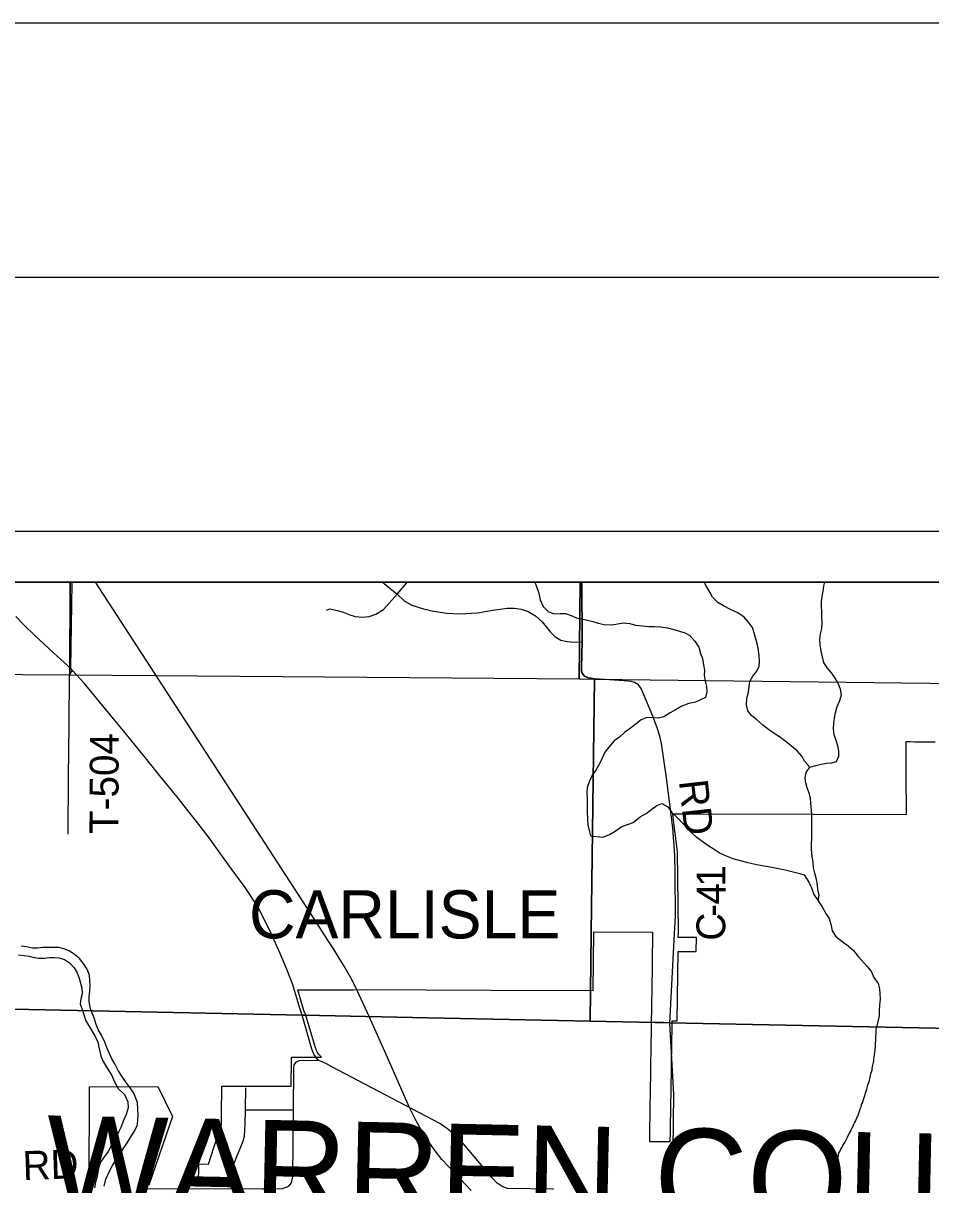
# Model space of a CAD drawing. Extents: x -7.3 to 34, y 0 to 22.
# Drawn here: x 3.68 to 5.466, y 19.714 to 22 of the extents above; entities that cross this region are included whole.
import ezdxf

# ---------------------------------------------------------------- set-up
doc = ezdxf.new("R2010")
doc.units = 0
for name, color, linetype in [('GM_X_City_Street', 7, 'Continuous'), ('GM_X_Corporation', 7, 'Continuous'), ('GM_X_Corporation_Text', 7, 'Continuous'), ('GM_X_County_Road', 7, 'Continuous'), ('GM_X_County_Road_Text', 7, 'Continuous'), ('GM_X_County_Text', 7, 'Continuous'), ('GM_X_Major_River', 7, 'Continuous'), ('GM_X_Minor_River', 7, 'Continuous'), ('GM_X_Rail_Line', 7, 'Continuous'), ('GM_X_State_Route', 7, 'Continuous'), ('GM_X_Township_Road', 7, 'Continuous'), ('GM_X_Township_Road_Text', 7, 'Continuous'), ('SH_Border', 7, 'Continuous'), ('SH_Cut_Line', 7, 'Continuous'), ('SH_Data', 7, 'Continuous')]:
    doc.layers.add(name, color=color, linetype=linetype)

msp = doc.modelspace()

# ---------------------------------------------------------------- linework, layer by layer
at = {"layer": 'GM_X_City_Street'}
for p, q in [((4.1178, 19.8612), (4.2121, 19.8615)), ((5.4549, 19.699), (5.4555, 19.7719))]:
    msp.add_line(p, q, dxfattribs=at)
msp.add_lwpolyline([(4.0902, 19.7065), (4.0892, 19.7344), (4.0911, 19.7458), (4.0946, 19.7551), (4.1131, 19.8), (4.1159, 19.8095), (4.1172, 19.833), (4.1178, 19.8612), (4.1185, 19.9047)], dxfattribs=at)
at = {"layer": 'GM_X_Corporation'}
for points in [[(2.7422, 20.0783), (4.2288, 20.048), (4.2328, 20.0479), (4.4762, 20.0428), (4.7954, 20.036), (4.9235, 20.0334), (4.9401, 20.0331), (4.9519, 20.0328), (5.8024, 20.0153), (5.9388, 20.0125), (6.0214, 20.0108), (6.0677, 20.0098), (6.0763, 20.0096), (6.4154, 20.0027), (6.4242, 20.0024), (6.9507, 19.9888), (6.9988, 19.9839), (7.6051, 19.9224), (7.8469, 19.8978), (8.8913, 19.7872), (8.9, 19.7858), (8.9, 20.9), (2.1, 20.9)], [(8.9, 20.9), (4.7796, 20.9), (4.7799, 20.7827), (4.7788, 20.7319), (4.7788, 20.7252), (4.7798, 20.7211), (4.7847, 20.7149), (4.7927, 20.7114), (4.804, 20.71), (4.7977, 20.2101), (4.7954, 20.036), (4.9235, 20.0334), (4.9401, 20.0331), (4.9519, 20.0328), (5.8024, 20.0153), (5.9388, 20.0125), (6.0214, 20.0108), (6.0677, 20.0098), (6.0763, 20.0096), (6.4154, 20.0027), (6.4242, 20.0024), (6.9507, 19.9888), (6.9988, 19.9839), (7.6051, 19.9224)], [(4.0254, 19.7132), (4.0256, 19.7549), (4.0446, 19.7548), (4.0553, 19.7873), (4.0612, 19.8053), (4.0659, 19.8198), (4.0701, 19.8323), (4.0703, 19.8512), (4.0706, 19.8702), (4.0708, 19.8891), (4.0711, 19.908), (4.1128, 19.9079), (4.1241, 19.9079), (4.1658, 19.9078), (4.2075, 19.9077), (4.2083, 19.9597), (4.2083, 19.9649), (4.254, 19.9651), (4.2672, 19.9653), (4.2656, 19.9665), (4.2636, 19.9681), (4.2621, 19.9698), (4.2612, 19.9712), (4.2595, 19.9742), (4.2575, 19.9779), (4.2564, 19.9806), (4.2554, 19.9837), (4.2354, 20.0499), (4.2347, 20.0502), (4.2327, 20.0567), (4.2203, 20.0974), (4.3008, 20.0977), (4.3242, 20.0979), (4.3301, 20.0979), (4.344, 20.098), (4.6011, 20.0967), (4.8019, 20.0965), (4.8029, 20.2118), (4.9168, 20.2113), (4.9185, 20.2112), (4.9182, 20.1896), (4.9182, 20.1887), (4.9179, 20.1706), (4.9179, 20.1698), (4.9177, 20.1516), (4.9177, 20.1508), (4.9174, 20.1326), (4.9174, 20.1319), (4.9171, 20.1136), (4.9171, 20.113), (4.9169, 20.0946), (4.9169, 20.094), (4.9166, 20.0756), (4.9166, 20.0751), (4.9163, 20.0566), (4.9163, 20.0562), (4.9159, 20.0378), (4.9156, 20.0212), (4.9156, 20.0189), (4.9154, 20.0045), (4.9153, 19.9999), (4.9151, 19.9878), (4.915, 19.981), (4.9148, 19.9711), (4.9147, 19.9602), (4.9146, 19.9545), (4.9145, 19.9507), (4.9143, 19.9378), (4.9142, 19.9317), (4.9141, 19.9211), (4.9139, 19.9128), (4.9138, 19.9044), (4.9136, 19.8939), (4.9136, 19.8884), (4.9133, 19.8749), (4.9133, 19.8712), (4.913, 19.856), (4.9128, 19.8408), (4.9127, 19.8371), (4.9126, 19.8257), (4.9125, 19.8181), (4.9122, 19.7992), (4.9516, 19.799), (4.9534, 19.799), (4.9537, 19.818), (4.954, 19.8369), (4.9543, 19.8558), (4.9546, 19.8748), (4.9549, 19.8937), (4.9552, 19.9126), (4.9555, 19.9316), (4.9558, 19.9505), (4.9559, 19.96), (4.9562, 19.9802), (4.9565, 19.9991), (4.9568, 20.0181), (4.9573, 20.0365), (4.963, 20.0364), (4.9668, 20.0363), (4.9668, 20.0365), (4.9687, 20.1733), (4.9977, 20.1729), (5.0043, 20.1728), (5.0043, 20.1736), (5.0047, 20.2003), (4.9986, 20.2004), (4.9981, 20.2004), (4.974, 20.2007), (4.9691, 20.2008), (4.9691, 20.2015), (4.9692, 20.2111), (4.9687, 20.2654), (4.9677, 20.369), (4.963, 20.4061), (4.9619, 20.4154), (4.9583, 20.4438), (4.9611, 20.4438), (4.9617, 20.4438), (4.9653, 20.4438), (4.9658, 20.4438), (4.9807, 20.4438), (4.9853, 20.4438), (5.2342, 20.4433), (5.4178, 20.4429), (5.4176, 20.5219), (5.4174, 20.5862), (5.4255, 20.5861), (5.4343, 20.586), (5.4746, 20.5855)], [(8.9, 14.1), (8.9, 19.7858), (8.8913, 19.7872), (7.8469, 19.8978), (7.6051, 19.9224), (6.9988, 19.9839), (6.9507, 19.9888), (6.4242, 20.0024), (6.4154, 20.0027), (6.0763, 20.0096), (6.0677, 20.0098), (6.0214, 20.0108), (5.9388, 20.0125), (5.8024, 20.0153), (4.9519, 20.0328), (4.9401, 20.0331), (4.9235, 20.0334), (4.7954, 20.036), (4.4762, 20.0428), (4.2328, 20.0479), (4.2288, 20.048), (2.7422, 20.0783)], [(8.9, 19.3924), (8.9, 19.7858), (8.8913, 19.7872), (7.8469, 19.8978), (7.6051, 19.9224), (6.9988, 19.9839), (6.9507, 19.9888), (6.4242, 20.0024), (6.4154, 20.0027), (6.0763, 20.0096), (6.0677, 20.0098), (6.0214, 20.0108), (5.9388, 20.0125), (5.8024, 20.0153), (4.9519, 20.0328), (4.9401, 20.0331), (4.9235, 20.0334), (4.7954, 20.036), (4.4762, 20.0428), (4.2328, 20.0479), (4.2288, 20.048), (2.7422, 20.0783)], [(3.81, 19.7128), (3.8109, 19.907), (3.9454, 19.9075), (3.974, 19.848), (3.9275, 19.713)]]:
    msp.add_lwpolyline(points, dxfattribs=at)
for points in [[(4.7796, 20.9), (2.1, 20.9), (2.1, 20.0921), (2.24, 20.0891), (2.7422, 20.0783), (4.2288, 20.048), (4.2328, 20.0479), (4.4762, 20.0428), (4.7954, 20.036), (4.7977, 20.2101), (4.804, 20.71), (4.7927, 20.7114), (4.7847, 20.7149), (4.7798, 20.7211), (4.7788, 20.7252), (4.7788, 20.7319), (4.7799, 20.7827)], [(3.7726, 20.9), (2.7489, 20.9), (2.7471, 20.7249), (3.7718, 20.7175)], [(4.7758, 20.9), (3.7726, 20.9), (3.7718, 20.7175), (4.7738, 20.7095)], [(5.7954, 20.9), (4.7758, 20.9), (4.7738, 20.7095), (4.8034, 20.7092), (5.7947, 20.6973)]]:
    msp.add_lwpolyline(points, close=True, dxfattribs=at)
at = {"layer": 'GM_X_County_Road'}
for p, q in [((4.78, 20.8372), (4.7799, 20.9)), ((4.9522, 20.0323), (4.961, 20.1956))]:
    msp.add_line(p, q, dxfattribs=at)
for points in [[(4.961, 20.1956), (4.9636, 20.2435), (4.9632, 20.3262), (4.9624, 20.3626), (4.9581, 20.4162), (4.9462, 20.5148), (4.9362, 20.5826), (4.9329, 20.5968), (4.9279, 20.6115), (4.9187, 20.6359), (4.9068, 20.6657), (4.8958, 20.6908), (4.8909, 20.6979), (4.8832, 20.7028), (4.8761, 20.7046), (4.8623, 20.7058), (4.8043, 20.7094), (4.793, 20.7109), (4.7849, 20.7143), (4.7801, 20.7206), (4.779, 20.7247), (4.779, 20.7314), (4.7802, 20.7822), (4.78, 20.8372)], [(4.9509, 19.6613), (4.9532, 19.6753), (4.9559, 19.7071), (4.9567, 19.7173), (4.9569, 19.7267), (4.959, 19.7831), (4.9606, 19.8921), (4.9522, 20.0323)]]:
    msp.add_lwpolyline(points, dxfattribs=at)
at = {"layer": 'GM_X_Major_River'}
msp.add_line((3.7966, 20.0567), (3.8141, 20.0563), dxfattribs=at)
for points in [[(3.6712, 20.1663), (3.6822, 20.165), (3.692, 20.1637), (3.7018, 20.1612), (3.7113, 20.1599), (3.7212, 20.1601), (3.7318, 20.161), (3.7413, 20.1612), (3.7508, 20.1607), (3.7614, 20.1571), (3.7712, 20.1508), (3.7808, 20.1412), (3.7864, 20.1312), (3.7903, 20.1205), (3.7928, 20.1109), (3.7953, 20.1006), (3.7962, 20.09), (3.7937, 20.0802), (3.7924, 20.0703), (3.7966, 20.0567)], [(3.8141, 20.0563), (3.8117, 20.0639), (3.81, 20.0738), (3.8098, 20.084), (3.8111, 20.095), (3.8117, 20.1053), (3.8111, 20.1159), (3.8106, 20.1258), (3.8066, 20.1373), (3.8003, 20.1476), (3.7911, 20.1592), (3.7813, 20.1674), (3.7708, 20.1744), (3.7603, 20.1784), (3.7505, 20.1808), (3.7288, 20.1812), (3.7189, 20.181), (3.7087, 20.1797), (3.6988, 20.1799), (3.6867, 20.182), (3.6764, 20.1833)], [(3.7966, 20.0567), (3.8037, 20.0367), (3.8132, 20.0205), (3.8219, 20.0059), (3.8276, 19.9932), (3.8282, 19.9873)], [(3.8396, 19.7115), (3.8426, 19.7248), (3.8499, 19.7409), (3.8559, 19.7521), (3.8633, 19.763), (3.8712, 19.7749), (3.8772, 19.7846), (3.8843, 19.7955), (3.8914, 19.8071), (3.9001, 19.8205), (3.905, 19.8322), (3.906, 19.8424), (3.9066, 19.8519), (3.9061, 19.8625), (3.905, 19.8762), (3.8979, 19.8942), (3.8909, 19.905), (3.8829, 19.9155), (3.8741, 19.9279), (3.8672, 19.939), (3.8607, 19.9521), (3.8538, 19.9629), (3.8495, 19.9733), (3.8445, 19.984), (3.8409, 19.9944), (3.8348, 20.0071), (3.828, 20.0198), (3.824, 20.0297), (3.8198, 20.0424), (3.8141, 20.0563)], [(3.8282, 19.9873), (3.8303, 19.9787), (3.8327, 19.968), (3.8377, 19.9565), (3.8453, 19.9434)], [(3.8453, 19.9434), (3.8544, 19.9287), (3.8598, 19.9165), (3.8674, 19.9037), (3.8796, 19.8913), (3.886, 19.8771), (3.8865, 19.8653), (3.8831, 19.8521), (3.8771, 19.8389), (3.873, 19.828), (3.8678, 19.8172), (3.8622, 19.8055), (3.8542, 19.7917), (3.8475, 19.7797), (3.84, 19.7693), (3.8325, 19.7584), (3.8284, 19.7464), (3.8257, 19.7309), (3.8224, 19.7192), (3.8206, 19.7082)]]:
    msp.add_lwpolyline(points, dxfattribs=at)
at = {"layer": 'GM_X_Minor_River'}
for points in [[(4.6871, 20.9), (4.6906, 20.8896), (4.6948, 20.8784), (4.6974, 20.8651), (4.703, 20.8523), (4.7129, 20.8425), (4.7241, 20.8376), (4.7367, 20.8383), (4.7473, 20.8383), (4.7582, 20.8345), (4.769, 20.8296), (4.7789, 20.8281), (4.7905, 20.8254), (4.8007, 20.8224), (4.8116, 20.819), (4.8233, 20.8164), (4.8381, 20.8162), (4.8503, 20.8181), (4.8606, 20.82), (4.8738, 20.8184), (4.8851, 20.8154), (4.912, 20.8126), (4.9226, 20.8126), (4.934, 20.8118), (4.9479, 20.8099), (4.9604, 20.8071), (4.9716, 20.8037), (4.9818, 20.8003), (4.9918, 20.7947), (5.0017, 20.7841), (5.0097, 20.7721), (5.0127, 20.7598), (5.0169, 20.7498), (5.0187, 20.7372), (5.0207, 20.7269), (5.0199, 20.7166), (5.0218, 20.7048), (5.0249, 20.6944), (5.0253, 20.6838), (5.0226, 20.6729), (5.0029, 20.6637), (4.9896, 20.6611), (4.9761, 20.6558), (4.9637, 20.649), (4.9529, 20.6426)], [(5.2276, 20.5361), (5.2183, 20.5469), (5.212, 20.5572), (5.2031, 20.568), (5.1915, 20.5774), (5.1788, 20.5875), (5.1683, 20.5953), (5.1574, 20.6023), (5.1466, 20.6097), (5.1357, 20.6183), (5.1234, 20.6287), (5.1133, 20.6373), (5.1062, 20.6469), (5.103, 20.6587), (5.1037, 20.6716), (5.1073, 20.6837), (5.1083, 20.6944), (5.11, 20.7046), (5.1155, 20.7147), (5.1233, 20.7248), (5.1284, 20.7346), (5.129, 20.7445), (5.1284, 20.7548), (5.1267, 20.7658), (5.124, 20.7795), (5.1211, 20.7906), (5.1183, 20.8005), (5.1154, 20.8108), (5.1069, 20.8209), (5.0987, 20.8313), (5.086, 20.8395), (5.072, 20.8462), (5.0581, 20.8533), (5.0472, 20.8599), (5.0364, 20.8707), (5.0305, 20.8815), (5.0247, 20.8915), (5.0199, 20.9)], [(5.2443, 20.273), (5.2463, 20.2839), (5.2439, 20.295), (5.2429, 20.3045), (5.2412, 20.3148), (5.238, 20.3274), (5.2352, 20.3377), (5.2343, 20.3495), (5.2326, 20.3597), (5.2313, 20.3738), (5.2311, 20.3841), (5.2317, 20.3958), (5.232, 20.4095), (5.2317, 20.4315), (5.2315, 20.441), (5.2309, 20.4509), (5.23, 20.4642), (5.2291, 20.4749), (5.2266, 20.4844), (5.2226, 20.4955), (5.2198, 20.5051), (5.2184, 20.515), (5.2205, 20.5256), (5.2276, 20.5361), (5.2394, 20.5393), (5.2501, 20.5417), (5.2608, 20.5434), (5.2703, 20.5444), (5.2806, 20.5473), (5.285, 20.5574), (5.2848, 20.5681), (5.2831, 20.578), (5.2798, 20.5883), (5.2755, 20.5998), (5.2742, 20.6112), (5.2752, 20.6222), (5.2765, 20.6328), (5.2782, 20.643), (5.2815, 20.6551), (5.2867, 20.6672), (5.2903, 20.6785), (5.2882, 20.6896), (5.2846, 20.6991), (5.278, 20.711), (5.2714, 20.7206), (5.2617, 20.7314), (5.2554, 20.7418), (5.2526, 20.7532), (5.2505, 20.7647), (5.2481, 20.7769), (5.2476, 20.7875), (5.2489, 20.7985), (5.2514, 20.8087), (5.252, 20.8197), (5.2518, 20.8323), (5.2513, 20.8425), (5.2507, 20.8524), (5.2509, 20.8619), (5.2522, 20.8718), (5.2539, 20.882), (5.2556, 20.8922), (5.2577, 20.9)], [(4.9529, 20.6426), (4.9408, 20.635), (4.9297, 20.6324), (4.9161, 20.6336), (4.9058, 20.6328), (4.8958, 20.6289), (4.8861, 20.6213), (4.8748, 20.6129), (4.8635, 20.6038), (4.8533, 20.5947), (4.8432, 20.5874), (4.8325, 20.5753), (4.8246, 20.5657), (4.8192, 20.5537), (4.8147, 20.544), (4.807, 20.5298), (4.7995, 20.5198), (4.7942, 20.5082), (4.7896, 20.4958), (4.7889, 20.4864), (4.7895, 20.473), (4.7898, 20.4586), (4.7898, 20.4483), (4.7905, 20.4331), (4.7912, 20.4221), (4.7935, 20.4114), (4.7962, 20.4006), (4.8208, 20.3983), (4.8323, 20.4025), (4.8447, 20.41), (4.8579, 20.4191), (4.871, 20.4236), (4.8806, 20.427), (4.8943, 20.4383), (4.9059, 20.4444), (4.9172, 20.4535), (4.9269, 20.4604), (4.9365, 20.4642), (4.9485, 20.4581), (4.9564, 20.4469), (4.9678, 20.4362), (4.9796, 20.4237), (4.9909, 20.4108), (5.0041, 20.3985), (5.0179, 20.3889), (5.029, 20.381), (5.0394, 20.3742), (5.0516, 20.3665), (5.0632, 20.3612), (5.0763, 20.3562), (5.091, 20.3519), (5.1034, 20.3488), (5.1147, 20.3462), (5.1268, 20.3439), (5.1532, 20.3392), (5.163, 20.3373), (5.1766, 20.3346), (5.1901, 20.3311), (5.2056, 20.3275), (5.2165, 20.3237), (5.2262, 20.3097), (5.2312, 20.2981), (5.236, 20.2854), (5.2443, 20.273), (5.2519, 20.261), (5.2594, 20.2478), (5.2656, 20.2381), (5.269, 20.227), (5.2716, 20.214), (5.2791, 20.2023), (5.291, 20.1932), (5.3032, 20.1844), (5.3135, 20.1753), (5.323, 20.1632), (5.3413, 20.1429), (5.3493, 20.1331), (5.3538, 20.1219), (5.3622, 20.1099), (5.3649, 20.0999), (5.3653, 20.0896), (5.3661, 20.0793), (5.3649, 20.0676), (5.3641, 20.0562), (5.3646, 20.0464), (5.3588, 20.0241)], [(5.3537, 19.9613), (5.3545, 19.9651), (5.355, 19.9681), (5.3554, 19.9715), (5.3558, 19.9741), (5.3563, 19.9779), (5.3564, 19.9817), (5.3568, 19.9851), (5.3569, 19.9878), (5.3573, 19.9905), (5.3574, 19.9931), (5.3579, 19.9973), (5.3575, 19.9999), (5.358, 20.0045), (5.3577, 20.0072), (5.3581, 20.0098), (5.3582, 20.0132), (5.3583, 20.0166), (5.3588, 20.0241)], [(5.272, 19.7123), (5.2732, 19.7153), (5.2737, 19.7191), (5.2745, 19.7221), (5.275, 19.7259), (5.2758, 19.7301), (5.2763, 19.7342), (5.2768, 19.7388), (5.2772, 19.7422), (5.2773, 19.7456), (5.2781, 19.7486), (5.279, 19.7524), (5.2798, 19.7558), (5.2806, 19.7588), (5.2814, 19.7618), (5.2822, 19.7645), (5.2827, 19.7671), (5.2843, 19.7713), (5.2852, 19.7766), (5.2871, 19.7796), (5.2891, 19.7841), (5.2915, 19.7878), (5.2931, 19.7912), (5.2966, 19.7972), (5.2986, 19.8014), (5.3006, 19.8047), (5.3022, 19.8078), (5.3034, 19.8111), (5.3057, 19.8153), (5.3077, 19.819), (5.3093, 19.8224), (5.3109, 19.8258), (5.3129, 19.8296), (5.3145, 19.8333), (5.316, 19.8359), (5.3176, 19.8393), (5.3188, 19.8423), (5.3204, 19.8457), (5.322, 19.8491), (5.324, 19.8552), (5.3261, 19.8604), (5.3277, 19.8657), (5.3293, 19.8691), (5.3297, 19.8717), (5.3313, 19.8755), (5.3329, 19.8797), (5.335, 19.8857), (5.3358, 19.8895), (5.337, 19.8921), (5.339, 19.8981), (5.3402, 19.9023), (5.3415, 19.9072), (5.3423, 19.9106), (5.3443, 19.9166), (5.3452, 19.92), (5.346, 19.9227), (5.3464, 19.9257), (5.3473, 19.9287), (5.3481, 19.9321), (5.3493, 19.9363), (5.3502, 19.9397), (5.3506, 19.9423), (5.3515, 19.9469), (5.3523, 19.9518), (5.3531, 19.9548), (5.3536, 19.9579), (5.3537, 19.9613)]]:
    msp.add_lwpolyline(points, dxfattribs=at)
at = {"layer": 'GM_X_Rail_Line'}
for points in [[(4.3609, 20.0449), (4.3374, 20.0966), (4.3276, 20.1166), (4.3199, 20.1305), (4.3118, 20.1444), (4.302, 20.1602), (4.292, 20.1765), (4.2795, 20.1952), (4.2529, 20.2371), (4.1809, 20.3478), (3.8228, 20.9)], [(4.5614, 19.7025), (4.5285, 19.7372), (4.5042, 19.764), (4.4886, 19.7837), (4.478, 19.7985), (4.4685, 19.8132), (4.4604, 19.8268), (4.4543, 19.8384), (4.4441, 19.8581), (4.4396, 19.8671), (4.3945, 19.9701), (4.3609, 20.0449)]]:
    msp.add_lwpolyline(points, dxfattribs=at)
at = {"layer": 'GM_X_State_Route'}
for points in [[(4.229, 20.0475), (4.2254, 20.0597), (4.2098, 20.1097), (4.1983, 20.1398), (4.1856, 20.1692), (4.1678, 20.2082), (4.1493, 20.247), (4.1409, 20.2622), (4.1167, 20.2987), (4.0893, 20.3367), (4.0674, 20.3674), (4.0481, 20.3944), (4.0284, 20.42), (3.9824, 20.4778), (3.9492, 20.5186), (3.9259, 20.5474), (3.8832, 20.6), (3.8523, 20.6384), (3.8398, 20.6532), (3.8, 20.7011), (3.7771, 20.726), (3.7737, 20.7298), (3.7543, 20.748), (3.74, 20.7611), (3.7034, 20.7948), (3.6812, 20.8161), (3.6656, 20.8323)], [(4.2604, 19.9595), (4.2523, 19.971), (4.2481, 19.9809), (4.229, 20.0475)], [(4.2697, 19.9554), (4.267, 19.9567), (4.2604, 19.9595)], [(4.7239, 19.7051), (4.7219, 19.7052), (4.6332, 19.7066), (4.6224, 19.7103), (4.6127, 19.7174), (4.603, 19.7278), (4.5463, 19.7946), (4.5364, 19.8052), (4.5242, 19.8162), (4.5154, 19.8235), (4.4997, 19.8345), (4.2872, 19.9463), (4.277, 19.9518), (4.2697, 19.9554)]]:
    msp.add_lwpolyline(points, dxfattribs=at)
at = {"layer": 'GM_X_Township_Road'}
for points in [[(3.7737, 20.7298), (3.7769, 20.8983), (3.7769, 20.9)], [(4.2768, 20.8446), (4.2834, 20.8472), (4.2983, 20.8443), (4.3098, 20.8409), (4.3228, 20.8355), (4.3335, 20.8321), (4.3475, 20.8311), (4.3609, 20.8325), (4.3741, 20.8371), (4.389, 20.8459), (4.4158, 20.8763), (4.4348, 20.8988), (4.436, 20.9)], [(4.3872, 20.9), (4.4158, 20.8763), (4.4301, 20.8632), (4.4447, 20.855), (4.4676, 20.8473), (4.4878, 20.8428), (4.5134, 20.8391), (4.5395, 20.8377), (4.5738, 20.8395), (4.6044, 20.8446), (4.6322, 20.8487), (4.6471, 20.8487), (4.6601, 20.8467), (4.6739, 20.8419), (4.6879, 20.8334), (4.701, 20.8221), (4.7175, 20.8015), (4.7261, 20.7932), (4.7383, 20.7859), (4.7504, 20.7832), (4.7635, 20.7821), (4.7802, 20.7822)], [(3.769, 20.4041), (3.7691, 20.5169), (3.7704, 20.6201), (3.7714, 20.7163), (3.7724, 20.7194), (3.7771, 20.726)], [(3.9243, 19.7062), (3.9253, 19.7062), (4.0902, 19.7065), (4.1508, 19.7059), (4.1745, 19.7059), (4.1907, 19.7065), (4.2031, 19.711), (4.2079, 19.7181), (4.2106, 19.7296), (4.2121, 19.8615), (4.2124, 19.9437), (4.2132, 19.9501), (4.2179, 19.9562), (4.2236, 19.9586), (4.2604, 19.9595)]]:
    msp.add_lwpolyline(points, dxfattribs=at)
at = {"layer": 'SH_Border'}
msp.add_lwpolyline([(1.5, 21.5), (33.5, 21.5), (33.5, 0.5), (1.5, 0.5)], close=True, dxfattribs=at)
at = {"layer": 'SH_Cut_Line'}
msp.add_lwpolyline([(0, 0), (34, 0), (34, 22), (0, 22)], close=True, dxfattribs=at)
at = {"layer": 'SH_Data'}
for p, q in [((2, 21), (9, 21)), ((2.1, 20.9), (8.9, 20.9))]:
    msp.add_line(p, q, dxfattribs=at)

# ---------------------------------------------------------------- texts
at = {"layer": 'GM_X_Corporation_Text'}
msp.add_text('CARLISLE', height=0.0947, rotation=0, dxfattribs=at).set_placement((4.1246, 20.1989))
at = {"layer": 'GM_X_County_Road_Text'}
for s, height, rotation, p in [('RD', 0.05682, 276.3942, (4.9702, 20.5085)), ('1', 0.0568, 90.5093, (5.062, 20.3007)), ('4', 0.0568, 90.29, (5.0622, 20.2654)), ('-', 0.0568, 89.7169, (5.0621, 20.2415)), ('C', 0.0568, 88.4699, (5.0608, 20.1935))]:
    msp.add_text(s, height=height, rotation=rotation, dxfattribs=at).set_placement(p)
at = {"layer": 'GM_X_County_Text'}
msp.add_text('WARREN COUNTY', height=0.189394, rotation=358.8222, dxfattribs=at).set_placement((3.7242, 19.6612))
at = {"layer": 'GM_X_Township_Road_Text'}
for s, rotation, p in [('T-504', 89.7236, (3.8674, 20.4043)), ('RD', 1.9738, (3.6801, 19.7232))]:
    msp.add_text(s, height=0.05682, rotation=rotation, dxfattribs=at).set_placement(p)

doc.saveas('drawing.dxf')
